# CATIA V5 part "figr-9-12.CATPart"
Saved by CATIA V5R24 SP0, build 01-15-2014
Part number: Part2
Bounding box of the stored display mesh (mm): x -96.75 to 0, y -83.031 to 83.031, z -58.031 to 58.031
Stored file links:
  D:\KAVITA\CATIA V5-6R2014 Project_ Kavita\CATIA V5-6R2014_partfiles\Partfiles\c09_catia_v5-6r2014_prt\figr-9-12.CATPart
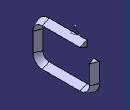
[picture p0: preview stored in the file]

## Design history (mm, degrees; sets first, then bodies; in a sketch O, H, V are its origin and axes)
Body1 (main body)
  Sketch1 on yz-plane, origin (0, 0, 0), H (0, 1, 0), V (0, 0, 1)
    point P1 (-75, 50)
    line L1 (-50, 50) -> (50, 50)
    line L2 (75, 25) -> (75, -25)
    line L3 (50, -50) -> (-50, -50)
    line L4 (-75, -25) -> (-75, 25)
    point P2 (75, 50)
    point P3 (75, -50)
    arc A1 centre (-50, 25) radius 25 from (-50, 50) to (-75, 25) ccw
    arc A2 centre (-50, -25) radius 25 from (-50, -50) to (-75, -25) cw
    arc A3 centre (50, -25) radius 25 from (50, -50) to (75, -25) ccw
    distance V L4 = 75
    distance H L1 = 50
    distance P1 P2 = 150
    radius A1 = 25
    radius A2 = 25
    distance P2 P3 = 100
    radius A3 = 25
    horizontal: L1 H, L3 H
    vertical: L2 V, L4 V
    coincidence: L1 P1, L4 P1, L3 P3, L2 P3, L2 P2, L1 P2
    tangency: A1 L1, A1 L4, A2 L3, A2 L4, A3 L3, A3 L2
  Plane1: type Angle, RefPlane yz-plane, Direction Sketch1.V, Angle 31
  Plane2: type Offset, RefPlane Plane1, Offset -108
  Sketch2 on Plane2, origin (-92.5741, -55.6241, 0), H (-0.515, 0.8572, 0), V (0, 0, 1)
    line L1 (0, 0) -> (-8.0309, -18.5626)
    line L2 (-8.0309, -18.5626) -> (8.1085, -18.5626)
    line L3 (8.1085, -18.5626) -> (0, 0)
    horizontal: L2 H
  Rib1: profile Sketch2, centre curve Sketch1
